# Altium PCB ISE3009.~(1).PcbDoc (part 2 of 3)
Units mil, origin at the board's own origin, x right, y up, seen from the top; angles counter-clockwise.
Board outline 2535 x 2952.76 mil, 4 copper layers (Top Layer, L2_P1, L3_P2, Bottom Layer), stack 90 mil thick; 177 components, 107 nets, 497 pads, 221 vias.
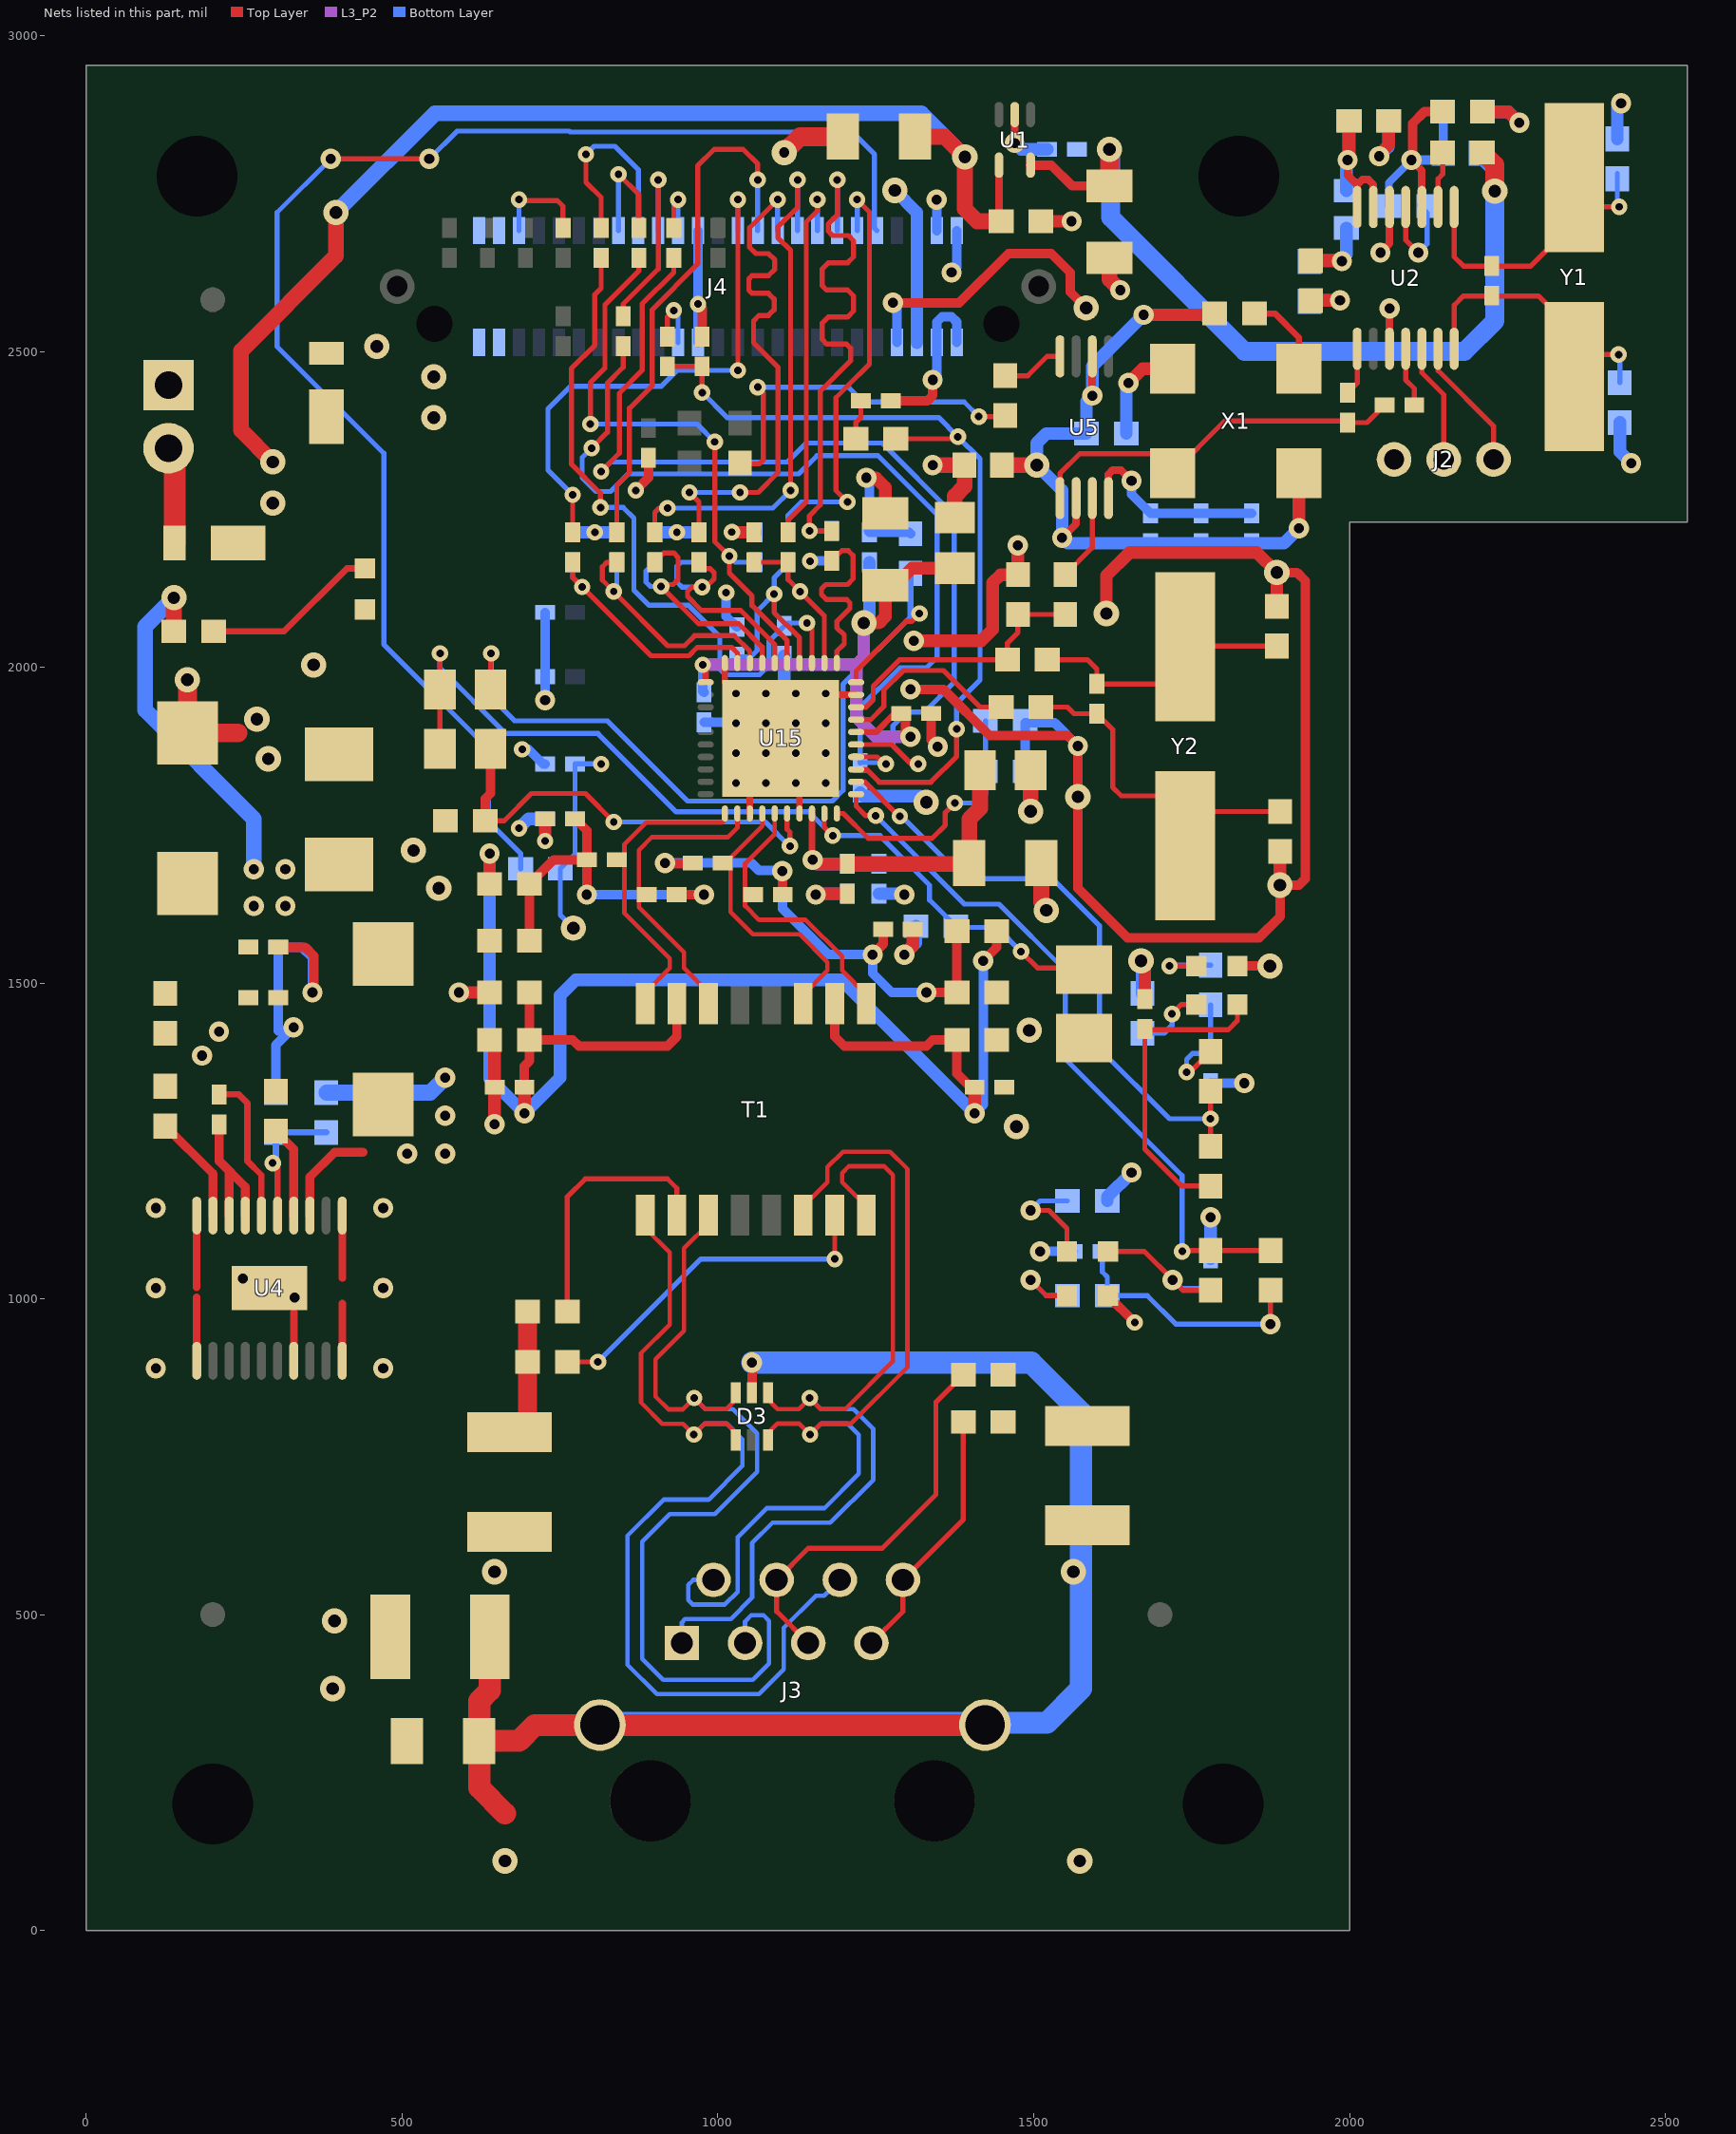
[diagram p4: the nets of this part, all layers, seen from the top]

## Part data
C1 C4: library part GRM319R61A105KA01D, "CAP CER 1UF 16V 10% X5R 1206"
C2 C7 C44: library part GRM188R70J224KA88D, "CAP CER 0.22UF 6.3V 10% X7R 0603"
C3 C9 C16 C21: "CAP, CERM, 33pF, 50V, +/-5%, C0G/NP0, 0603"
C5: "CAP, CERM, 0.1uF, 16V, +80/-20%, Y5V, 0603"
C8: library part GRM1555C1H150JA01D, "CAP CER 15PF 50V 5% NP0 0402"
C10 C20 C48 C54: "CAP, CERM, 0.01uF, 50V, +/-10%, C0G/NP0, 0402"
C11 C49: "CAP, CERM, 39pF, 25V, +/-5%, C0G/NP0, 0402"
C12 C17 C25 C32: "CAP, CERM, 100pF, 50V, +/-10%, X7R, 0402"
C13 C24: "CAP, CERM, 10uF, 35V, +/-10%, X7R, 1206"
C18 C29: "CAP, TA, 100uF, 10V, +/-20%, 0.6 ohm, SMD"
C22 C47 C51 C53 C55: "CAP, CERM, 0.1uF, 16V, +/-10%, X7R, 0603"
C23 C26 C36 C37: "CAP, CERM, 0.1uF, 10V, +/-10%, X5R, 0402"
C27 C31 C33 C34: "CAP, CERM, 1uF, 6.3V, +/-10%, X5R, 0603"
C28 C42 C46 C50 C52: "CAP, CERM, 1000pF, 25V, +/-10%, X5R, 0402"
C30: "CAP, TA, 10uF, 16V, +/-10%, 2 ohm, SMD"
C35: "CAP, CERM, 0.22uF, 16V, +/-10%, X7R, 0603"
C38 C39: "CAP, CERM, 1000pF, 2000V, +/-10%, X7R, 1812"
C40: "CAP, CERM, 4700pF, 2000V, +/-10%, X7R, 1812"
C41 C43 C45: "CAP, CERM, 4.7uF, 6.3V, +/-10%, X5R, 0603"
D1 D2: "Diode, Schottky, 200V, 1A, PowerDI123"
D3: "Quad Channel High Speed ESD Protection Device, DCK0006A"
D4: "Diode, Zener, 3.9V, 550mW, SMB"
FB1 FB2 FB3: library part MMZ1608B102C, "FERRITE CHIP 1000 OHM 300MA 0603"
FB4 R12 R18 R19 R29 R33 R35 R41 R44 R45 R46 R47 R51 R52 R53 R61 R78 R79 R84: "RES, 0 ohm, 5%, 0.1W, 0603"
FID1 FID2 FID3 FID4 FID5 FID6: "Fiducial mark.  There is nothing to buy or mount."
J1: "CONN TERM BLOCK 2.54MM 2POS PCB"
J2: "CONN HEADER 3POS 2MM VERT T/H"
J3: library part RJ45_NOMAG_NOLED, "CONN MOD JACK R/A 8P8C SHIELDED"
J4: "Receptacle, 0.8mm, 25x2, SMT"
LBL1: library part THT-14-423-10, "Thermal Transfer Printable Labels, 0.650\" W x 0.200\" H - 10,000 per roll"
LD1 LD2 LD3 LD4 LD5: "LED SmartLED Green 570NM"
Logo1: library part TI_Logo, "Texas Instrument Corporate Signature"
MH1 MH2 MH3 MH4: library part "MH 3_0.5MM", "Mountin hole, NPTH Drill 3.2mm"
R1 R2 R3 R4 R5 R6 R7 R10 R11 R23 R24 R25 R26 R27 R28 R62: "RES, 100 ohm, 5%, 0.063W, 0402"
R8: "RES, 0 ohm, 5%, 0.063W, 0402"
R9 R36: "RES, 1.00Meg ohm, 1%, 0.063W, 0402"
R13: "RES, 33 ohm, 5%, 0.063W, 0402"
R14 R15: "RES, 22 ohm, 5%, 0.063W, 0402"
R16 R50 R63 R64 R65 R66 R67 R68 R69 R70 R71 R72 R75 R77 R81 R82 R100: "RES, 2.2k ohm, 5%, 0.063W, 0402"
R17: "RES, 100 ohm, 5%, 0.1W, 0603"
R21 R30 R34 R38: "RES, 0 ohm, 5%, 0.125W, 0805"
R31 R59 R60: "RES, 4.7k ohm, 5%, 0.1W, 0603"
R32 R49 R76 R80 R83: "RES, 470 ohm, 1%, 0.1W, 0603"
R39 R40 R42 R43: "RES, 49.9 ohm, 1%, 0.063W, 0402"
R48: "RES, 3.3k ohm, 5%, 0.063W, 0402"
R54 R55 R56 R57: "RES, 75.0 ohm, 1%, 0.1W, 0603"
R58: "RES, 1.0Meg ohm, 5%, 0.25W, 1206"
R73: "RES, 4.87k ohm, 1%, 0.1W, 0603"
R74: "RES, 2.00k ohm, 1%, 0.063W, 0402"
T1: "TRANSFORMER, MDL, XFMR SGL ETHR LAN, SOIC-16"
TP1 TP2: "Test Point 40mil pad 20mil drill"
U1: library part TPS71533DCK, "IC REG LDO 1.8V 50MA SC70-5"
U2: "Programmable 1-PLL VCXO Clock Synthesizer With 1.8-V, 2.5-V, and 3.3-V Outputs, PW0014A"
U4: "IC, Low Dropout Voltage Regulator, 3.3 V, 2.0 A"
U5: "3.3 V and 2.5 V LVCMOS High-Performance Clock Buffer Family, PW0008A"
U15: library part DP83848J, "TI DP83848J 10/100 PHY"
X1: "OSC 25.00 MHZ 3.3V HIGH STAB SMD"
Y1 Y2: library part XTAL-NX5032GA, "CRYSTAL 25.0MHZ 18PF SMD"
ZZ1: library part AssemblyNoteLabel
ZZ2 ZZ3 ZZ4: library part AssemblyNote

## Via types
v1: diameter 26, hole 12, Top Layer to Bottom Layer, tented both sides, 104 vias
v2: diameter 32, hole 16, Top Layer to Bottom Layer, tented both sides, 80 vias
v3: diameter 40, hole 20, Top Layer to Bottom Layer, tented both sides, 36 vias
v4: diameter 40, hole 16, Top Layer to Bottom Layer, tented both sides, 1 vias

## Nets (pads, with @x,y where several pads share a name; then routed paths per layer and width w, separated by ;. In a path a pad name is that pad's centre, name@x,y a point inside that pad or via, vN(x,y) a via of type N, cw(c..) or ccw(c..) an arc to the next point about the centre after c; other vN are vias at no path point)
1.8V: C4.1 C42.1 FB1.1 R59.2 U1.5 | length 1364.6
  Top Layer w15: U1.5@1495,2795 1528,2795 1560.91,2762.09 C4.1@1620,2762.09
  Top Layer w30: C4.1@1620,2762.09 v3(1620,2820) ; R59.2@2210.5,2815 2230,2795.5 v3(2230,2754)
  Bottom Layer w30: v3@1622,2820 1622,2712 1834,2500 2182,2500 2230,2548 v3(2230,2754) 2230,2791.53 FB1.1@2207.53,2814
1_5V_PS: J4.44 TP2.1 | length 457.6
  Top Layer w15: v2(1277,2577) 1382,2577 1460,2655 1528,2655 1558,2625 1558,2594 TP2.1@1583,2569
  Bottom Layer w15: v2(1277,2577) 1283.47,2570.53 J4.44@1283.47,2514.17
3_3V_PS: C18.1 C20.1 C28.1 C32.1 C44.2 C45.2 D4.1 FB3.1 FB4.2 R21.1 R32.2 R38.1 R45.2 R49.2 R50.2 R63.2 R64.2 R65.2 R66.2 R67.2 R70.2 R74.1 R75.2 R80.2 R82.2 R100.2 | length 1600.5
  Top Layer w20: v2(590,1485) R45.2@638.5,1485 ; v1(1022,2214) 1025.24,2214 1025.62,2213.62 R100.2@1057,2213.62 ; v3(1670,1535) 1676,1529 R50.2@1676,1474.62 ; C45.2@1939,2580.5 v2@1988.5,2580.5
  Top Layer w25: R32.2@138.5,2056.85 v3(138.5,2110) ; v2(1340,2320) FB3.1@1390.47,2320 1390.47,2286.32 1375,2270.85 R21.1@1375,2236.85 ; v3(1495,1771.85) R38.1@1495,1836.85
  Bottom Layer w15: v1(1013,2118) 1013,2080.62 R70.2@1030,2063.62
  Bottom Layer w20: v1(685,1745) 700,1760 R75.2@726.38,1760 ; R67.2@770,2213.62 R66.2@840,2213.62 ; R65.2@900,2213.62 R64.2@970,2213.62 ; v1(1022,2214) 1025.24,2214 1025.62,2213.62 R63.2@1059,2213.62 ; R74.1@1225,1801.38 1230.38,1796 1320,1796 v3(1330,1786) ; R80.2@1616.5,1155 1616.5,1161.5 v2(1655,1200) ; v3(1670,1535) 1672,1533 R49.2@1672,1483.5 ; R82.2@1780,1063.62 v2(1780,1129) ; C44.2@1939.01,2581 v2@1989,2581
  Bottom Layer w25: v3(138.5,2110) 93,2064.5 93,1932 265,1760 v2(265,1680)
  other v1: 805,2213.62 935,2213.62
  other v2: 265,1622 315,1622 315,1680 1985,2581
3_3V_PS_E: FB4.1 J4.45 J4.46 R47.2 | length 255.3
  Bottom Layer w20: v3(1280,2755) 1314.97,2720.03 J4.45@1314.97,2691.34 J4.46@1314.97,2514.17
  other v2: 183,1385 210,1423
5V_PS: C1.1 C5.1 C29.1 C35.2 D1.1 D2.1 R78.1 U1.4 U4.3 U4.4 | length 2397.4
  Top Layer w12: C5.1@1445,2709.5 U1.4@1445,2795
  Top Layer w14: C35.2@300,1265.35 328.39,1236.96 U4.4@328.39,1131.85 ; U4.3@353.98,1131.85 353.98,1192.83 393,1231.85 438,1231.85
  Top Layer w25: v3(295,2325) 245,2375 245,2501 395,2651 v3(395,2720) ; C1.1@1312.09,2840 1359,2840 v3(1391,2808) 1391,2725.5 1410.5,2706 C5.1@1448.5,2706
  Bottom Layer w25: R78.1@380,1326.5 544.5,1326.5 v2(568,1350) ; v3(395,2720) 552,2877 1322,2877 v3(1391,2808)
  other v2: 508,1230 568,1230 568,1290
  other v3: 295,2260
25M_50M_REF: R18.2 R61.1 | length 569.7
  Top Layer w8: R18.2@1038,2321.85 1065.5,2321.85 1072,2328.35 1072,2434.35 v1(1063,2443.35) ; v1(1413,2396.85) R61.1@1458,2396.85
  Bottom Layer w8: v1(1063,2443.35) 1206.98,2443.35 1230.32,2420 1389.85,2420 v1(1413,2396.85)
AVDD33: C24.1 C25.1 C52.1 C54.1 R38.2 U15.18 | length 579.8
  Top Layer w10: v2@1148.9,1696.1 U15.18@1148.9,1768.41
  Top Layer w20: v2@1148.9,1696.1 v2(1150,1695) 1156.38,1688.62 C25.1@1205,1688.62
  Top Layer w25: C25.1@1205,1688.62 1205.27,1688.35 1384.41,1688.35 1397.91,1701.85 1397.91,1759.76 1415,1776.85 R38.2@1415,1836.85
  Bottom Layer w20: v2(1150,1695) 1156.38,1688.62 C52.1@1205,1688.62 C54.1@1255,1688.62
CLOCK_Y3: R14.2 R15.2 U5.1 X1.3 | length 624
  Top Layer w8: U5.1@1541.61,2267.8 1541.61,2306.61 1573,2338 1689.32,2338 X1.3@1720,2307.32 1802.68,2390 R15.2@1997,2390 ; R15.2@1997,2387.38 2027.76,2387.38 R14.2@2055.38,2415
COL: R6.1 R63.1 U15.35 | length 946.5
  Top Layer w8: v1(798,2385) 798,2450.57 821,2473.57 821,2574 875,2628 R6.1@875,2648.23 ; v1(995,2356.85) 995,2199 v1(1018,2176) 1018,2149 1054,2113 1054,2097.63 1109.53,2042.1 U15.35@1109.53,2006.59
  Bottom Layer w8: v1(798,2385) 966.85,2385 v1(995,2356.85) ; v1(1018,2176) 1027.62,2166.38 R63.1@1059,2166.38
CRS: R5.1 R69.2 U15.33 | length 1090.5
  Top Layer w8: v1(814,2253) 814,2275.64 768,2321.64 768,2473 805,2510 805,2590 815,2600 R5.1@815,2648.23 ; v1(1141,2070) 1148.9,2062.1 U15.33@1148.9,2006.59
  Bottom Layer w8: v1(814,2253) 850,2253 867,2236 867,2122 891,2098 953.45,2098 1003,2048.45 1003,1997 1012,1988 1065.89,1988 1081,2003.11 1081,2041.47 R69.2@1105,2065.47 1109.53,2070 v1(1141,2070)
CT_INPUT: C33.1 C34.1 C36.1 C37.1 R41.1 R44.1 R45.1 T1.2 T1.7 | length 2628.2
  Top Layer w15: C36.1@693.62,1335 693.62,1368.62 701.5,1376.5 C34.1@701.5,1410 ; R45.1@701.5,1485 C34.1@701.5,1410 ; T1.7@935,1467.52 935,1415 920,1400 780,1400 770,1410 C34.1@701.5,1410 ; T1.2@1185,1467.52 1185,1415 1200,1400 1330,1400 1340,1410 C33.1@1378.5,1410 1378.5,1356.5 1400,1335 C37.1@1406.38,1335 ; v2(1420,1535) 1441.5,1556.5 R44.1@1441.5,1581.85
  Top Layer w20: R41.1@638.5,1656.85 v2(638.5,1705) ; v2(693.62,1293.62) C36.1@693.62,1335 ; v2(1406.38,1293.62) C37.1@1406.38,1335
  Bottom Layer w15: v2(1406.38,1293.62) 1420,1307.24 v2(1420,1535)
  Bottom Layer w20: v2(638.5,1705) 638.5,1348.74 v2(693.62,1293.62) 750,1350 750,1480 775,1505 1195,1505 v2(1406.38,1293.62)
EARTH: C38.2 C39.2 C40.2 D3.2 J3.SH1 J3.SH2 R58.2 | length 2937.3
  Top Layer w15: D3.2@1054,851.4 v2(1054,899)
  Top Layer w35: C40.2@638.74,465 638.74,380 622.09,363.35 R58.2@622.09,300 ; 663,185 622.09,225.91 R58.2@622.09,300 ; J3.SH1@1415.91,325.08 J3.SH2@813.05,325.08 710.08,325.08 685,300 R58.2@622.09,300
  Bottom Layer w35: J3.SH2@813.05,325.08 816.54,328.57 J3.SH1@1419.4,328.57 ; v2(1054,899) 1496,899 1575,820 1575,382.85 1520.72,328.57 J3.SH1@1419.4,328.57 ; J3.SH1@1422.89,325.08 J3.SH1@1419.4,328.57
  other v3: 663,110 1572.95,110 646.43,567.85 1563,567.85
ENO_INT: J4.41 R84.1 | length 2335.7
  Top Layer w8: v2(387,2805) v2(543,2805)
  Bottom Layer w8: v2(387,2805) 302,2720 302,2507.85 471,2338.85 471,2036.37 637,1870.37 637,1756 687.5,1705.5 R84.1@687.5,1681 ; v2(543,2805) 587,2849 764.5,2849 766,2847.5 1212.5,2847.5 1248,2812 1248,2695.31 J4.41@1251.97,2691.34
GND: C1.2 C2.1 C3.2 C4.2 C5.2 C7.1 C8.2 C9.2 C10.2 C11.2 C12.2 C13.2 C16.2 C17.2 C18.2 C20.2 C21.2 C22.2 C23.2 C24.2 C25.2 C26.2 C27.2 C28.2 C29.2 C30.2 C31.2 C32.2 C33.2 C34.2 C35.1 C36.2 C37.2 C40.1 C41.1 C42.2 C43.1 C46.2 C47.2 C48.2 C49.2 C50.2 C51.1 C52.2 C53.2 C54.2 C55.2 D4.2 J1.1 J2.3 J4.23 J4.24 J4.47 J4.48 J4.49 J4.50 LD1.1 LD2.1 LD5.1 R16.2 R31.1 R58.1 R68.1 R69.1 R71.1 R72.1 R73.1 R77.2 R79.1 R81.2 U1.2 U2.5 U2.10 U4.1 U4.10 U4.11 U4.17 U4.20 U4.21 U5.4 U15.13 U15.17 U15.29 U15.40 U15.41 X1.2 | length 7493.4
  Top Layer w10: U15.40@1011.1,2006.59 1011.1,1975.84 U15.41@1099.44,1887.5 ; U15.13@1050.47,1768.41 1050.47,1838.53 U15.41@1099.44,1887.5 ; U15.41@1123.19,1863.76 U15.41@1099.44,1887.5 ; U15.17@1129.21,1768.41 U15.41@1129.21,1857.73 ; U15.29@1218.78,1956.4 1168.34,1956.4 U15.41@1099.44,1887.5
  Top Layer w12: U4.11@174.84,901.85 174.84,1002.69 ; 174.84,1018.01 U4.10@174.84,1131.85 ; U4.17@328.39,901.85 328.39,978.46 ; U4.20@405.16,901.85 405.16,992.69 ; 405.16,1032.84 U4.1@405.16,1131.85 ; v2(1470,2830) U1.2@1470,2875 ; U5.4@1618.39,2267.8 1618.39,2305.39 1625,2312 1638,2312 v2(1655,2295) ; v2(2049,2656.5) 2063.41,2670.91 U2.5@2063.41,2728.71 ; U2.10@2063.41,2504.3 v2(2063.41,2568)
  Top Layer w15: C28.2@303.62,1556.85 346.15,1556.85 360,1543 v2@360,1492.85 ; v1(870,2280) 890,2300 C11.2@890,2331.38 ; v1(968.51,2575) 975,2568.51 C8.2@975,2523.62 ; R16.2@1273.62,2421.85 1331.85,2421.85 1340,2430 v2(1340,2455) ; v2(1305,1965) 1356.85,1965 1430,1891.85 1553.42,1891.85 v2(1570,1875.27) v3(1570,1794.85) 1570,1650 1648.15,1571.85 1856.85,1571.85 1890,1605 v3(1890,1655) 1920,1655 1930,1665 1930,2136.85 1916.85,2150 v3(1885,2150) ; C17.2@1337.62,1927 1337.62,1884.38 v2(1348,1874) ; LD5.1@1617.48,1005 v1(1660,962.48) ; LD2.1@1822.48,1526.85 1873.85,1526.85 v3(1874,1527)
  Top Layer w20: C34.2@638.5,1410 646.38,1402.13 C36.2@646.38,1335 v2(646.38,1276.38) ; v1(726.38,1725) C23.2@726.38,1760 ; v2@1156.38,1641.38 C25.2@1205,1641.38 ; v2(1235,2300) 1250,2300 1265,2285 C13.2@1265,2243.94 ; v2(1295,1545) 1308.62,1558.62 C26.2@1308.62,1585 ; v2(1310,2042) 1417,2042 1435,2060 1435,2134 1447.5,2146.5 R31.1@1475,2146.5 v2@1475,2190 ; C5.2@1511.5,2706 v2(1560,2706) ; v3(1615,2085) 1615,2145 1651.85,2181.85 1853.15,2181.85 v3(1885,2150) C16.2@1885,2096.5 ; v2(1650,2450) 1672.68,2472.68 X1.2@1730,2472.68 ; v3(1890,1655) C21.2@1890,1708.5 ; v2(2047,2809) 2047,2812 2062.5,2827.5 C7.1@2062.5,2865 ; C2.1@2210.5,2879.5 2251.5,2879.5 v2(2269,2862)
  Top Layer w25: C24.2@1512.09,1690 1512.09,1627.91 1520,1620 v3(1520,1615) ; C4.2@1620,2647.91 1620,2614 v2(1637,2597)
  Top Layer w30: v3(160,1980) C18.2@160,1895.94 240,1895.94 ; v4(1105,2815) 1130,2840 C1.2@1197.91,2840
  Bottom Layer w12: v1(1146,2168) v1@1146.38,2168.38
  Bottom Layer w15: R79.1@300,1326.5 300,1402 v2@322.23,1424.23 ; v2(328,1430) v2@322.23,1424.23 ; v2(358,1485) 358,1540 341.15,1556.85 C20.2@303.62,1556.85 303.62,1424.23 v2@322.23,1424.23 ; v1(690,1870) 700,1870 723.15,1846.85 R72.1@726.38,1846.85 ; v2(726.38,1948) R71.1@726.38,1985 R68.1@726.38,2086.85 ; J4.24@968.51,2514.17 v1(968.51,2575) J4.23@968.51,2691.34 ; C50.2@978,1912.76 1027.18,1912.76 v1(1028.82,1911.12) ; v1@1146.38,2168.38 C49.2@1180,2168.38 ; v2(1235,2300) 1240,2295 C48.2@1240,2213.62 ; C48.2@1238,2215.62 C48.2@1240,2213.62 ; C47.2@1305,2211.5 1302.87,2213.62 C48.2@1240,2213.62 ; v2(1340,2455) 1346.46,2461.46 J4.48@1346.46,2514.17 1346.46,2546.46 1355,2555 1370,2555 1377.96,2547.04 J4.50@1377.96,2514.17 ; J4.47@1346.46,2691.34 v2(1346.46,2740.31) ; v2(1370,2625) 1377.96,2632.96 J4.49@1377.96,2691.34 ; R73.1@1486.5,1836.85 1486.5,1911.85 1533.42,1911.85 v2(1570,1875.27) ; v2(1510,1075) R81.2@1561.38,1075 ; v2(1655,2295) 1655,2273.62 C10.2@1685,2243.62 C46.2@1765,2243.62 C12.2@1845,2243.62 ; R77.2@1780,1341.38 v2(1833.62,1341.38)
  Bottom Layer w20: v1(1076.06,1958.37) 1105,1958.37 R69.1@1105,2018.23 ; v2(1155,1640) 1156.38,1641.38 C52.2@1205,1641.38 ; C54.2@1255,1641.38 1293.62,1641.38 v2(1295,1640) ; v2(1295,1545) 1313.5,1563.5 C53.2@1313.5,1590 ; v2(1470,2830) 1480,2820 C42.2@1521.38,2820 ; C55.2@1646.5,2370 1646.5,2446.5 v2(1650,2450) ; v2(2047,2809) 2061.5,2823.5 C43.1@2061.5,2865 ; C41.1@2210.5,2879.5 2251.5,2879.5 v2(2269,2862) ; C3.2@2424,2836.5 2424,2887 v2(2430,2893) ; C9.2@2428,2387.5 2428,2341 v2(2446,2323)
  other v1: 1028.82,1816.63 1076.06,1816.63 1123.31,1816.63 1170.55,1816.63 1028.82,1863.88 1076.06,1863.88 1123.31,1863.88 1170.55,1863.88 1076.06,1911.12 1123.31,1911.12 1170.55,1911.12 1028.82,1958.37 1123.31,1958.37 1170.55,1958.37
  other v2: 110,890 470,890 330,1002 110,1016.85 470,1016.85 248,1032 110,1143.7 470,1143.7 1475,2193
  other v3: 390,382.85 393,490 1472.5,1272.85 1493,1425 558,1650 518,1710 288,1855 270,1917.85 360,2003.7
IOVDD33: C13.1 C17.1 C48.1 C50.1 R21.2 U15.1 U15.26 | length 987
  Top Layer w10: v1(976,2004) 980.59,1999.41 U15.1@980.59,1976.08 ; U15.26@1218.78,1897.34 1250.34,1897.34 1279.85,1926.85 1290.38,1926.85 C17.1@1290.38,1927
  Top Layer w15: C17.1@1290.38,1926.85 1297,1920.23 1297,1895 v2@1302,1890
  Top Layer w20: v3(1231,2070) 1255,2070 1265,2080 C13.1@1265,2129.76 1280.2,2129.76 1307.28,2156.85 R21.2@1375,2156.85
  L3_P2 w20: v1(976,2004) 1219,2004 1219,1921 1250,1890 v2@1302,1890 ; 1219.41,2003.59 1231,2015.17 v3(1231,2070)
  Bottom Layer w15: v1(976,2004) 976,1962 C50.1@978,1960
  Bottom Layer w20: v3@1240,2081.85 C48.1@1240,2166.38
  other v2: 1305,1890
LED_LINK: R46.2 R51.1 U15.22 | length 983.5
  Top Layer w8: U15.22@1218.78,1818.6 1232.17,1818.6 1286.77,1764 v1(1288,1764) ; R51.1@1780,1241.5 v1(1780,1285) R46.2@1780,1328.5
  Bottom Layer w8: v1(1288,1764) 1291,1764 1390,1665 1530,1665 1604,1591 1604,1396 1715,1285 v1(1780,1285)
LED_SPEED: R52.1 R53.2 U15.21 | length 1120
  Top Layer w8: U15.21@1218.78,1798.92 1218.78,1780.22 1234,1765 v1(1250,1765) ; v1(1735,1075) 1736.5,1076.5 R52.1@1780,1076.5 R53.2@1875,1076.5
  Bottom Layer w8: v1(1250,1765) 1390,1625 1445,1625 1550,1520 1550,1380 1735,1195 v1(1735,1075)
MDC: R7.1 U15.25 | length 1591
  Top Layer w8: v1(815,2310) 844,2339 844,2434 880,2470 880,2575 930,2625 R7.1@930,2648.23 ; U15.25@1218.78,1877.66 1275.34,1877.66 1306,1847 v1(1317,1847)
  Bottom Layer w8: v1(815,2310) 830,2325 1110,2325 1140,2355 1260,2355 1374,2241 1374,1976 1327,1929 1299,1929 1277,1907 1277,1876 1303,1850 v1@1314,1850
MDIO: R11.1 R74.2 U15.24 | length 1430
  Top Layer w8: v1(800,2347) 825,2372 825,2450 850,2475 R11.1@850,2508.23 ; U15.24@1218.78,1857.97 1252.03,1857.97 1261,1849 1264,1849 v1(1266,1847)
  Bottom Layer w8: v1(800,2347) 785,2332 785,2300 806.82,2278.18 830,2278.18 857.82,2306 1127.87,2306 1156.87,2335 1253.13,2335 1347,2241.13 1347,2016 1330,1999 1288,1999 1225,1936 R74.2@1225,1848.62 1225.38,1849 1264,1849 v1(1266,1847)
NetC2_2: C2.2 C41.2 FB1.2 R60.2 U2.3 | length 403.7
  Top Layer w12: v2(2098,2803) 2114.59,2786.41 U2.3@2114.59,2728.71
  Top Layer w15: v2(2098,2803) 2100,2805 2100,2861 2118.5,2879.5 C2.2@2147.5,2879.5
  Bottom Layer w12: R60.2@2062.33,2730.15 2062.33,2767.33 v2(2098,2803)
  Bottom Layer w15: v2(2098,2803) 2137.47,2803 FB1.2@2148.47,2814 2148.47,2878.53 C41.2@2147.5,2879.5
NetC3_1: C3.1 R9.2 U2.1 Y1.1 | length 518.1
  Top Layer w8: U2.1@2165.77,2728.71 2165.77,2649.73 2180.38,2635.13 2287.13,2635.13 2356,2704 Y1.1@2356,2785.32 ; Y1.1@2356,2749 2376,2729 v1(2427,2729)
  Bottom Layer w8: C3.1@2424,2781.5 2424,2732 v1(2427,2729)
NetC7_2: C7.2 C43.2 FB2.2 U2.6 U2.7 | length 323.3
  Top Layer w12: v2(1997,2803) 1997,2779 2012.23,2763.77 ; U2.7@2012.23,2728.71 2012.23,2763.77 ; U2.6@2037.82,2728.71 2037.82,2764.18 2030,2772 2020.46,2772 2012.23,2763.77
  Top Layer w20: v2(1997,2803) 1999.5,2805.5 C7.2@1999.5,2865
  Bottom Layer w20: FB2.2@1995,2754.53 1995,2801 v2(1997,2803) 1998.5,2804.5 C43.2@1998.5,2865
NetC9_1: C9.1 R9.1 U2.14 Y1.2 | length 493.2
  Top Layer w8: U2.14@2165.77,2504.3 2165.77,2573.28 2180.38,2587.88 2299.12,2587.88 2356,2531 Y1.2@2356,2450.68 ; Y1.2@2356,2474 2377,2495 v1(2426,2495)
  Bottom Layer w8: v1(2426,2495) 2428,2493 C9.1@2428,2450.5
NetC10_1: C10.1 C12.1 C46.1 C55.1 FB3.2 R12.1 U5.2 U5.6 X1.4 | length 1259.6
  Top Layer w12: v2(1545,2205) 1567.2,2227.2 U5.2@1567.2,2267.8 ; v2(1592.8,2430) U5.6@1592.8,2492.2
  Top Layer w20: v2(1674,2558) 1784.5,2558 R12.1@1786.5,2556 ; v2(1920,2220) 1920,2297.32 X1.4@1930,2307.32
  Top Layer w25: FB3.2@1449.53,2320 v3(1505,2320)
  Bottom Layer w20: v2(1674,2558) 1592.8,2476.8 v2(1592.8,2430) 1583.5,2420.71 C55.1@1583.5,2370 1520,2370 1505,2355 v3(1505,2320) 1545,2280 v2(1545,2205) 1553.62,2196.38 C10.1@1685,2196.38 C46.1@1765,2196.38 C12.1@1845,2196.38 1896.38,2196.38 v2(1920,2220)
NetC16_1: C16.1 R33.2 R36.2 Y2.1 | length 465.3
  Top Layer w8: R33.2@1521.5,2011.85 1585,2011.85 1600,1996.85 R36.2@1600,1973.62 1740,1973.62 Y2.1@1740,2042.32 1748.82,2033.5 C16.1@1885,2033.5
NetC21_1: C21.1 R35.2 R36.1 Y2.2 | length 642.7
  Top Layer w8: R35.2@1511.5,1936.85 1553.15,1936.85 1563.62,1926.38 R36.1@1600,1926.38 1625,1901.38 1625,1810 1638.74,1796.26 Y2.2@1740,1796.26 Y2.2@1740,1707.68 1740,1771.5 C21.1@1890,1771.5
NetC23_1: C23.1 C27.1 R40.1 R41.2 R42.1 | length 553.5
  Top Layer w15: C27.1@701.5,1566.85 R41.2@701.5,1656.85 739.65,1695 R40.1@792.38,1695 ; C23.1@773.62,1760 792.38,1741.24 R40.1@792.38,1695 ; v2(792.38,1640) R40.1@792.38,1695 ; R42.1@934.62,1640 v2(978,1640)
  Bottom Layer w15: v2(792.38,1640) v2(978,1640)
NetC26_1: C26.1 C31.1 R39.1 R43.1 R44.2 | length 825.9
  Top Layer w15: v2(916,1690) 917,1689 R39.1@960.38,1689 ; R43.1@1102.62,1640 v2@1102.62,1677 ; v2(1245,1545) 1261.38,1561.38 C26.1@1261.38,1585 ; v2(1330,1485) C31.1@1378.5,1485 R44.2@1378.5,1581.85
  Bottom Layer w15: v2(916,1690) 1053,1690 1065,1678 1102.62,1678 1102.62,1617.38 1175,1545 v2(1245,1545) 1245,1515 1275,1485 v2(1330,1485)
  other v2: 1102,1677
NetC38_1: C38.1 R55.1 R57.1
NetC39_1: C39.1 R54.1 R56.1 | length 211.1
  Top Layer w30: C39.1@670,788.74 683.74,788.74 698.5,803.5 R56.1@698.5,900 R54.1@698.5,980
NetC44_1: C44.1 C45.1 FB2.1 | length 150.6
  Top Layer w20: C45.1@1939,2643.5 v2@1988,2643.5
  Bottom Layer w20: C44.1@1939,2644 1985,2644 1995,2654 FB2.1@1995,2695.47
  other v2: 1988,2643
NetD1_2: D1.2 J4.1 J4.2 J4.3 J4.4
  other v3: 550,2395 550,2460 460,2507.85
NetD2_2: D2.2 J1.2 | length 154.1
  Top Layer w35: J1.2@130,2346.85 139.8,2337.05 D2.2@139.8,2196.85
NetJ2_1: J2.1 U2.13 | length 211.7
  Top Layer w8: U2.13@2140.18,2504.3 2140.18,2469.82 2228,2382 J2.1@2228,2329
NetJ2_2: J2.2 U2.12 | length 189.7
  Top Layer w8: U2.12@2114.59,2504.3 2114.59,2466.41 2149.3,2431.7 J2.2@2149.3,2329
NetJ3_4: J3.4 J3.5 R55.2 | length 636.7
  Top Layer w8: J3.5@1142.97,455 1092.97,505 J3.4@1092.97,555 1142.97,605 1260,605 1345,690 1345,836.5 R55.2@1388.5,880
NetJ3_7: J3.7 J3.8 R57.2 | length 410.3
  Top Layer w8: J3.7@1242.97,455 1292.97,505 J3.8@1292.97,555 1388.5,650.53 R57.2@1388.5,805
NetJ4_5: J4.5 R4.2 | length 156.8
  Top Layer w8: v1(685.04,2740.31) 686.35,2739 745.53,2739 754.53,2730 R4.2@754.53,2695.94
  Bottom Layer w8: J4.5@685.04,2691.34 v1(685.04,2740.31)
NetJ4_15: J4.15 R6.2 | length 187.7
  Top Layer w8: v1(842.52,2780.52) 875,2748.05 R6.2@875,2695.47
  Bottom Layer w8: J4.15@842.52,2691.34 v1(842.52,2780.52)
NetJ4_17: J4.17 R5.2 | length 326.8
  Top Layer w8: v1(791,2812) 791,2768 815,2744 R5.2@815,2695.47
  Bottom Layer w8: v1(791,2812) 804,2825 837,2825 874.02,2787.98 J4.17@874.02,2691.34
NetJ4_19: J4.19 R11.2 | length 319.8
  Top Layer w8: R11.2@850,2555.47 850,2575 905.52,2630.52 v1(905.52,2771.81)
  Bottom Layer w8: J4.19@905.52,2691.34 v1(905.52,2771.81)
NetJ4_21: J4.21 R7.2 | length 96.7
  Top Layer w8: R7.2@930,2695.47 930,2733.3 v1(937.01,2740.31)
  Bottom Layer w8: J4.21@937.01,2691.34 v1(937.01,2740.31)
NetJ4_22: J4.22 R13.1 | length 99.3
  Top Layer w8: R13.1@920,2523.62 920,2555 v1(930,2565)
  Bottom Layer w8: v1(930,2565) 937.01,2557.99 J4.22@937.01,2514.17
NetJ4_35: J4.35 R23.2 | length 594.9
  Top Layer w8: R23.2@1111,2213.62 1111,2233 1140,2262 1140,2705 1157.49,2722.49 v1(1157.49,2740.31)
  Bottom Layer w8: J4.35@1157.49,2691.34 v1(1157.49,2740.31)
NetJ4_39: J4.39 R62.2 | length 694.9
  Top Layer w8: v1(1205,2261.85) 1186.82,2280.03 1186.82,2426.82 1205.66,2445.66 1240,2480 1240,2720.79 v1(1220.48,2740.31)
  Bottom Layer w8: R62.2@1111,2213.62 1111,2240.64 1132.21,2261.85 v1(1205,2261.85) ; J4.39@1220.48,2691.34 v1(1220.48,2740.31)
NetLD1_2: LD1.2 R32.1 | length 280.8
  Top Layer w10: R32.1@201.5,2056.85 313,2056.85 412.63,2156.48 LD1.2@441,2156.48
NetLD2_2: LD2.2 R76.2 | length 108.1
  Top Layer w8: v1(1715,1526.85) LD2.2@1757.52,1526.85
  Bottom Layer w8: v1(1715,1526.85) 1716.5,1528.35 R76.2@1780,1528.35
NetLD3_1: LD3.1 R50.1 R51.2 | length 497.2
  Top Layer w8: R51.2@1780,1178.5 1734.5,1178.5 1676,1237 R50.1@1676,1427.38 1677.38,1426 1808,1426 1822.48,1440.48 LD3.1@1822.48,1466
NetLD3_2: LD3.2 R49.1 | length 114.9
  Top Layer w8: v1(1719,1451) 1734,1466 LD3.2@1757.52,1466
  Bottom Layer w8: R49.1@1672,1420.5 1706.5,1420.5 1719,1433 v1(1719,1451)
NetLD4_1: LD4.1 R52.2 R82.1 | length 253.6
  Top Layer w8: LD4.1@1617.48,1075 1675,1075 v2(1720,1030) 1736.5,1013.5 R52.2@1780,1013.5
  Bottom Layer w8: v2(1720,1030) 1733.62,1016.38 R82.1@1780,1016.38
NetLD4_2: LD4.2 R80.1 | length 170.5
  Top Layer w8: v2(1495,1140) 1524,1140 1552.52,1111.48 LD4.2@1552.52,1075
  Bottom Layer w8: v2(1495,1140) 1510,1155 R80.1@1553.5,1155
NetLD5_2: LD5.2 R83.2 | length 136.7
  Top Layer w8: v2(1495,1030) 1520,1005 LD5.2@1552.52,1005
  Bottom Layer w8: v2(1495,1030) 1520,1005 R83.2@1553.5,1005
NetR12_2: R12.2 X1.1 | length 135.6
  Top Layer w10: R12.2@1849.5,2560 1882,2560 1920,2522 X1.1@1920,2472.68
NetR14_1: R14.1 U2.11 | length 94.9
  Top Layer w8: U2.11@2089,2504.3 2089,2455 2102.62,2441.38 R14.1@2102.62,2415
NetR15_1: R15.1 U2.8 | length 76
  Top Layer w8: R15.1@1997,2434.62 2012.23,2449.85 U2.8@2012.23,2504.3
NetR16_1: R16.1 R19.1 | length 63.3
  Top Layer w8: R19.1@1218.5,2361.85 1218.5,2387.54 1226.38,2395.41 R16.1@1226.38,2421.85
NetR29_1: R29.1 U5.3 | length 124
  Top Layer w8: R29.1@1550,2146.5 1592.8,2189.29 U5.3@1592.8,2252.8
NetR29_2: R29.2 R31.2 R33.1 U15.28 | length 437
  Top Layer w8: U15.28@1218.78,1936.71 1234.34,1936.71 1246,1948.37 1246,1970 1287.85,2011.85 R33.1@1458.5,2011.85 1458.5,2038.5 1475,2055 R31.2@1475,2083.5 R29.2@1550,2083.5
NetR35_1: R35.1 U15.27 | length 301.2
  Top Layer w8: U15.27@1218.78,1917.03 1242.03,1917.03 1262.63,1937.63 1262.63,1963.63 1293.85,1994.85 1357,1994.85 1415,1936.85 R35.1@1448.5,1936.85
NetR46_1: R46.1 R76.1 R77.1 | length 190.2
  Top Layer w8: v1(1742,1359) 1747.5,1359 R46.1@1780,1391.5
  Bottom Layer w8: v1(1742,1359) 1742,1379 1751.62,1388.62 R77.1@1780,1388.62 R76.1@1780,1465.35
NetR47_1: R47.1 R48.2 U4.7 U4.8 U4.9 | length 405.8
  Top Layer w14: R47.1@125,1273.5 200.43,1198.07 U4.9@200.43,1131.85 ; 210,1218 210,1219 ; R48.2@210,1276.38 210,1219 ; U4.8@226.02,1131.85 226.02,1201.98 ; U4.7@251.61,1131.85 251.61,1177.39 210,1219
NetR48_1: R48.1 U4.6 | length 238
  Top Layer w10: R48.1@210,1323.62 241.38,1323.62 255,1310 255,1218.23 277.2,1196.03 U4.6@277.2,1131.85
NetR53_1: R53.1 R81.1 R83.1 | length 403.9
  Top Layer w8: v2(1875,960) R53.1@1875,1013.5
  Bottom Layer w8: R81.1@1608.62,1075 1608.62,1042.64 1616.5,1034.77 R83.1@1616.5,1005 1680,1005 1725,960 v2(1875,960)
NetR54_2: R54.2 T1.10 | length 415.5
  Top Layer w8: R54.2@761.5,980 761.5,1161.5 790,1190 920,1190 935,1175 T1.10@935,1132.48
NetR56_2: R56.2 T1.15 | length 560.5
  Top Layer w8: R56.2@761.5,900 v1(810,900) ; v1(1185,1063) T1.15@1185,1132.48
  Bottom Layer w8: v1(810,900) 973,1063 v1(1185,1063)
NetR59_1: R59.1 U2.2 | length 86.3
  Top Layer w8: U2.2@2140.18,2728.71 2140.18,2773.18 2147.5,2780.5 R59.1@2147.5,2812
NetR60_1: R60.1 U2.4 | length 166.5
  Top Layer w8: U2.4@2089,2728.71 2089,2676.5 v2(2109,2656.5)
  Bottom Layer w8: v2(2109,2656.5) 2123,2670.5 2123,2719 R60.1@2110.5,2731.5
NetR61_2: R61.2 U5.8 | length 99.3
  Top Layer w8: R61.2@1455,2461.5 1490.63,2461.5 1521.34,2492.2 U5.8@1541.61,2492.2
NetR72_2: R72.2 R75.1 R84.2 TP1.1 | length 317.5
  Bottom Layer w8: TP1.1@771,1587 750.5,1607.5 R84.2@750.5,1681 773.62,1704.13 R75.1@773.62,1760 ; R75.1@773.62,1761.85 R72.2@773.62,1846.85 v1(815,1846.85)
NetR78_2: R78.2 R79.2 U4.5 | length 217
  Top Layer w10: v1(295,1215) 302.8,1207.2 U4.5@302.8,1131.85
  Bottom Layer w10: v1(295,1215) 300,1220 R79.2@300,1263.5 R78.2@380,1263.5
PFBIN1: C22.1 R34.2 U15.16 | length 705.7
  Top Layer w8: C22.1@631.5,1756.85 661.5,1756.85 704.64,1800 790,1800 v1(835,1755) ; U15.16@1109.53,1768.41 1109.53,1743.47 1114,1739 v1(1114,1717)
  Top Layer w15: C22.1@631.5,1756.85 631.5,1791.5 640,1800 R34.2@640,1871
  Bottom Layer w8: v1(835,1755) 1075,1755 1113,1717 v1(1114,1717)
PFBIN2: C47.1 R30.2 U15.30 | length 1302.9
  Top Layer w8: R30.2@640,1965 640,2021 v1(641,2022) ; U15.30@1218.78,1976.08 1218.78,1993.78 1297.5,2072.5 1306.5,2072.5 v1(1319,2085)
  Bottom Layer w8: v1(641,2022) 641,1952 678,1915 825,1915 952,1788 1181,1788 1198,1805 1198,1973 1305,2080
  Bottom Layer w10: 1305,2080 C47.1@1305,2148.5
PFBOUT: C30.1 C53.1 R30.1 R34.1 U15.19 | length 1445
  Top Layer w8: R34.1@560,1871 R30.1@560,1965 v1(560,2022) ; U15.19@1168.58,1768.41 1168.58,1746.42 v1(1181.63,1733.37) ; v1(1480,1550) 1506.06,1523.94 C30.1@1580,1523.94
  Bottom Layer w8: v1(560,2022) 560,1999 664,1895 810,1895 934,1771 1144,1771 v1(1181.63,1733.37) 1256.63,1733.37 1335,1655 1335,1631.5 C53.1@1376.5,1590 1378.5,1588 1442,1588 v1(1480,1550)
RBIAS: C51.2 R73.2 U15.20 | length 408.6
  Top Layer w8: U15.20@1188.27,1768.41 1198.59,1768.41 1238,1729 1339,1729 1360,1750 1360,1770 v1(1375,1785)
  Bottom Layer w8: v1(1375,1785) 1410,1785 1423.5,1798.5 R73.2@1423.5,1835 C51.2@1423.5,1915
RDM_B: R40.2 T1.8 U15.11 | length 495.3
  Top Layer w7: R40.2@839.62,1695 R40.2@852,1695 ; T1.8@885,1467.52 885,1485 923.5,1523.5 923.5,1538.97 852,1610.47 R40.2@852,1695 ; U15.11@1011.1,1768.41 1011.1,1758.63 1006.47,1754 886,1754 852,1720 R40.2@852,1695
RDP_B: R42.2 T1.6 U15.12 | length 493.9
  Top Layer w7: R42.2@887.38,1640 R42.2@875,1640 ; T1.6@985,1467.52 985,1485 946.5,1523.5 946.5,1548.5 875,1620 R42.2@875,1640 ; U15.12@1030.79,1768.41 1030.79,1745.79 1016,1731 895.53,1731 875,1710.47 R42.2@875,1640
RESET_N: C8.1 R13.2 R19.2 U15.23 | length 1350.6
  Top Layer w8: R13.2@920,2476.38 C8.1@975,2476.38 v1(975,2435) ; U15.23@1218.78,1838.29 1235.11,1838.29 1255.4,1818 1337,1818 1378,1859 v1(1378,1902) ; R19.2@1281.5,2361.85 1376.85,2361.85 v1(1380,2365)
  Bottom Layer w8: v1(975,2435) 1014.59,2395.41 1349.59,2395.41 v1(1380,2365) 1415,2330 1415,1980 1378,1943 v1(1378,1902)
RX+_RJ45: D3.3 J3.3 T1.11 | length 1459.4
  Top Layer w7: T1.11@985,1132.48 985,1118.78 946.5,1080.28 946.5,949.47 901.26,904.24 901.26,845.26 921.53,825 945,825 962.5,842.5 v1(962.5,843) 980,825.5 1013.5,825.5 1028.41,840.41 D3.3@1028.41,851.4
  Bottom Layer w7: v1(962.5,843) 980,825.5 1023.53,825.5 1062,787.03 1062,726 995,659 923.53,659 880,615.47 880,430 913,397 1055.47,397 1081.11,422.64 1081.11,490 1072.22,498.89 1052.63,498.89 1042.97,489.23 J3.3@1042.97,455
RX-_RJ45: D3.4 J3.6 T1.9 | length 1564.7
  Top Layer w7: T1.9@885,1132.48 885,1112.04 923.5,1073.54 923.5,959 878.26,913.76 878.26,835.74 912,802 945,802 v1(962,785) 979.5,802.5 1013.5,802.5 1028.41,787.59 D3.4@1028.41,776.6
  Bottom Layer w7: v1(962,785) 979.5,802.5 1014,802.5 1039,777.5 1039,735.53 985.47,682 914,682 857,625 857,420.47 903.47,374 1065,374 1104.11,413.11 1104.11,479.11 1155,530 1167.97,530 J3.6@1192.97,555
RX_CLK: R24.1 U15.31 | length 310.8
  Top Layer w8: R24.1@1180,2168.23 1196.5,2184.72 1206.28,2184.72 1214,2177 1214,2140 1205,2131 1171,2131 1164,2124 1164,2115 1172,2107 1204,2107 1209,2102 1209,2093.25 1188.27,2072.52 1188.27,2062.73 1200,2051 1200,2037 1188.27,2025.27 U15.31@1188.27,2006.59
RX_CLK_1: C49.1 J4.37 R24.2 | length 924.5
  Top Layer w8: R24.2@1180,2215.47 1145.53,2215.47 v1(1145,2216) 1145,2240 1162,2257 1162,2437 1210,2485 1210,2505 1203.5,2511.5 1172.5,2511.5 1165.26,2518.74 1165.26,2545.26 1174.5,2554.5 1205,2554.5 1214.74,2564.24 1214.74,2587.76 1205,2597.5 1171.5,2597.5 1165.26,2603.74 1165.26,2630.76 1175,2640.5 1205.5,2640.5 1214.74,2649.74 1214.74,2675.26 1206.5,2683.5 1181.5,2683.5 1174.36,2690.64 1174.36,2701.36 1188.98,2715.98 v1(1188.98,2771.81)
  Bottom Layer w8: v1(1145,2216) 1145.38,2215.62 C49.1@1180,2215.62 ; J4.37@1188.98,2691.34 v1(1188.98,2771.81)
RX_DV: R23.1 R100.1 U15.32 | length 237.5
  Top Layer w8: R100.1@1057,2166.38 R23.1@1111,2166.38 1111,2138.87 v1(1130,2119.87) 1168.35,2081.53 U15.32@1168.35,2006.59
RX_ER: R62.1 R70.1 U15.34 | length 323.6
  Top Layer w8: v1(1089,2116) 1089,2086.64 1129.21,2046.43 U15.34@1129.21,2006.59
  Bottom Layer w8: R70.1@1030,2016.38 1051.88,2016.38 1062,2026.5 1062,2089 v1(1089,2116) 1089,2141.5 R62.1@1113.88,2166.38
RXD0: R28.1 R64.1 U15.36 | length 404
  Top Layer w8: R28.1@970,2166.38 980.38,2156 988,2156 994,2150 994,2140 980.85,2126.85 v1(975,2126.85) 974.85,2127 959,2127 952,2120 952,2112 974,2090 1036,2090 1089.84,2036.16 U15.36@1089.84,2006.59
  Bottom Layer w8: R64.1@970,2166.38 941.38,2166.38 935,2160 935,2135 943.15,2126.85 v1(975,2126.85)
RXD1: R27.1 R65.1 U15.37 | length 401.8
  Top Layer w8: R27.1@900,2166.38 914.62,2181 930,2181 937,2174 937,2139 929,2131 913,2131 v1(910,2128) 969.15,2068.85 1033.15,2068.85 1070.16,2031.84 U15.37@1070.16,2006.59
  Bottom Layer w8: R65.1@900,2166.38 886,2152.38 886,2135 893,2128 v1(910,2128)
RXD2: R26.1 R66.1 U15.38 | length 408.1
  Top Layer w8: R26.1@840,2166.38 839.62,2166 824,2166 817,2159 817,2138 v1(835,2120) 835,2119.4 920.4,2034 947,2034 963,2050 1026,2050 1050.47,2025.53 U15.38@1050.47,2006.59
  Bottom Layer w8: v1(835,2120) 840,2125 R66.1@840,2166.38
RXD3: R25.1 R67.1 U15.39 | length 407.1
  Top Layer w8: R25.1@770,2166.38 770,2142 v1(785,2127) 894,2018 954,2018 967.39,2031.39 1021.61,2031.39 1030.79,2022.21 U15.39@1030.79,2006.59
  Bottom Layer w8: R67.1@770,2166.38 770,2142 v1(785,2127)
RXD_0: J4.31 R28.2 | length 853.5
  Top Layer w8: v1(955,2276.85) 970,2261.85 R28.2@970,2213.62 ; v1(1035,2276.85) 1063.85,2276.85 1095,2308 1095,2475 1056.5,2513.5 1056.5,2548.48 1065,2556.98 1080,2556.98 1089,2565.98 1089,2583 1080,2592 1054,2592 1049,2597 1049,2615 1050,2616 ; 1050,2615 1050,2616 ; v1(1094.49,2740.31) 1050,2695.82 1050,2665 1060,2655 1080,2655 1090,2645 1090,2630 1080,2620 1054,2620 1050,2616
  Bottom Layer w8: v1(955,2276.85) v1(1035,2276.85) ; J4.31@1094.49,2691.34 v1(1094.49,2740.31)
RXD_1: J4.33 R27.2 | length 854.3
  Top Layer w8: R27.2@900,2213.62 900,2245 906.85,2251.85 v1(920,2251.85) ; v1(1115,2280) 1115,2660 1095,2680 1095,2697.01 1125.99,2728 v1(1125.99,2771.81)
  Bottom Layer w8: v1(920,2251.85) 1086.85,2251.85 v1(1115,2280) ; J4.33@1125.99,2691.34 v1(1125.99,2771.81)
RXD_2: J4.29 R26.2 | length 854.4
  Top Layer w8: R26.2@840,2213.62 840,2288 860,2308 860,2410.12 896,2446.12 896,2566.36 968,2638.36 968,2794 994,2820 1040,2820 1063,2797 v1(1063,2771.81)
  Bottom Layer w8: J4.29@1063,2691.34 v1(1063,2771.81)
RXD_3: J4.27 R25.2 | length 856.6
  Top Layer w8: R25.2@770,2213.62 v1(770,2273.15) ; v1(1031.5,2470) v1(1031.5,2740.31)
  Bottom Layer w8: v1(770,2273.15) 731,2312.15 731,2409 767,2445 910.5,2445 935.5,2470 v1(1031.5,2470) ; J4.27@1031.5,2691.34 v1(1031.5,2740.31)
TDM_A: R39.2 T1.3 U15.14 | length 444.5
  Top Layer w7: U15.14@1070.16,1768.41 1070.16,1748.68 1020,1698.53 1020,1690 1020,1612.47 1055.47,1577 1129.47,1577 1173.5,1532.97 1173.5,1519.72 1135,1481.22 T1.3@1135,1467.52
TDP_A: R43.2 T1.1 U15.15 | length 455.5
  Top Layer w7: R43.2@1055.38,1640 R43.2@1043,1640 ; U15.15@1089.84,1768.41 1089.84,1735.84 1043,1689 R43.2@1043,1640 ; T1.1@1235,1467.52 1235,1481.22 1196.5,1519.72 1196.5,1542.5 1139,1600 1065,1600 1043,1622 R43.2@1043,1640
TX+_RJ45: D3.1 J3.1 T1.16 | length 1410.1
  Top Layer w7: D3.1@1079.59,851.4 1079.59,840.41 1094.5,825.5 1128,825.5 v1(1145.5,843) 1163,825.5 1201.5,825.5 1277,901 1277,1196 1263,1210 1207.5,1210 1196.5,1199 1196.5,1184.68 1235,1146.18 T1.16@1235,1132.48
  Bottom Layer w7: J3.1@942.97,455 942.97,487.97 948,493 1020.53,493 1054.11,526.58 1054.11,613.11 1086.47,645.47 1178,645.47 1246,713.47 1246,794.03 1214.53,825.5 1163,825.5 v1(1145.5,843)
TX-_RJ45: D3.6 J3.2 T1.14 | length 1472.8
  Top Layer w7: D3.6@1079.59,776.6 1079.59,787.59 1094.5,802.5 1128.5,802.5 v1(1146,785) 1163.5,802.5 1211.03,802.5 1300,891.47 1300,1205.53 1272.53,1233 1197.97,1233 1173.5,1208.53 1173.5,1184.68 1135,1146.18 T1.14@1135,1132.48
  Bottom Layer w7: J3.2@992.97,555 961,555 953,547 953,523 960,516 1011,516 1031.11,536.11 1031.11,622.64 1076.95,668.47 1168.47,668.47 1223,723 1223,784.5 1205,802.5 1163.5,802.5 v1(1146,785)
